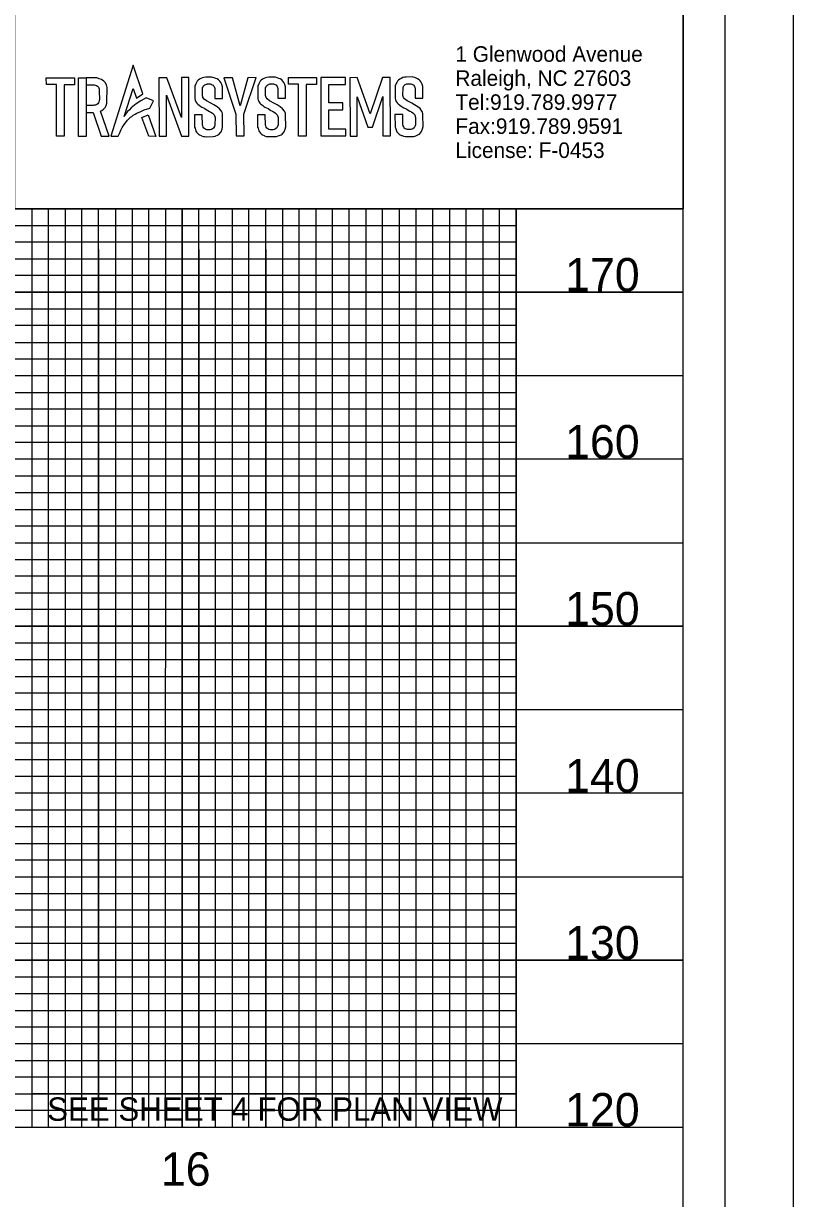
# Model space of a CAD drawing. Extents: x 1779926 to 1781626, y 618464 to 619564.
# Drawn here: x 1781395.5 to 1781626, y 619017.9 to 619369.7 of the extents above; entities that cross this region are included whole.
import ezdxf

# ---------------------------------------------------------------- set-up
doc = ezdxf.new("R2010")
doc.units = 0
for name, color, linetype in [('Exist Vertical Profile Horizontal Axis Label Major', 7, 'Continuous'), ('Exist Vertical Profile Vertical Axis Label', 7, 'Continuous'), ('Old_Level_2', 7, 'Continuous'), ('Old_Level_58', 7, 'Continuous'), ('Prop DSN Text', 7, 'Continuous'), ('Prop Grid Mask', 7, 'Continuous'), ('Prop VPI Ditch Grade Right Label', 7, 'Continuous'), ('Sheet DOT Grid CELL', 7, 'Continuous'), ('Sheet Layout Profile Border Port 1', 7, 'Continuous'), ('Sheet Plot Border Inside CELL', 7, 'Continuous'), ('Sheet Plot Border Outside CELL', 7, 'Continuous'), ('Sheet Profile CELL', 7, 'Continuous'), ('Sheet Profile Grid Major CELL', 7, 'Continuous'), ('Sheet Profile Grid Middle CELL', 7, 'Continuous'), ('Sheet Profile Grid Minor CELL', 7, 'Continuous')]:
    doc.layers.add(name, color=color, linetype=linetype)

msp = doc.modelspace()

# ---------------------------------------------------------------- linework, layer by layer
at = {"layer": 'Old_Level_58'}
msp.add_lwpolyline([(1781392.9, 619378.14), (1781592.95, 619378.14), (1781592.95, 619314.19), (1781392.9, 619314.19)], close=True, dxfattribs=at)
at = {"layer": 'Prop Grid Mask'}
msp.add_lwpolyline([(1781542.96, 619049.19), (1781397.96, 619049.19), (1781397.96, 619039.19), (1781542.96, 619039.19)], close=True, dxfattribs=at)
at = {"layer": 'Prop VPI Ditch Grade Right Label'}
for points in [[(1781428.25, 619357.23), (1781421.58, 619335.89), (1781423.81, 619335.9), (1781424.15, 619336.74), (1781424.72, 619337.9), (1781425.03, 619338.53), (1781425.41, 619339.07), (1781425.93, 619339.83), (1781426.26, 619340.3), (1781426.64, 619340.69), (1781427.02, 619341.08), (1781427.51, 619341.58), (1781427.92, 619341.85), (1781428.33, 619342.18), (1781428.89, 619342.5), (1781429.38, 619342.78), (1781430.6, 619343.35), (1781431.6, 619343.76), (1781433.24, 619344.32), (1781434.38, 619346.46), (1781432.2, 619347.42), (1781430.57, 619346.53), (1781429.19, 619345.63), (1781428.21, 619344.83), (1781427.69, 619344.41), (1781427.15, 619343.84), (1781426.62, 619343.27), (1781426.22, 619342.85), (1781425.84, 619342.2), (1781425.63, 619341.84), (1781428.26, 619350.22), (1781429.26, 619347.33), (1781431.16, 619348.58)], [(1781402.29, 619353.38), (1781410.75, 619353.39), (1781410.75, 619351.31), (1781407.64, 619351.31), (1781407.66, 619335.89), (1781405.31, 619335.89), (1781405.29, 619351.41), (1781402.32, 619351.41)], [(1781411.91, 619353.37), (1781414.22, 619353.38), (1781414.24, 619335.81), (1781411.92, 619335.81)], [(1781414.22, 619351.29), (1781416.61, 619351.29), (1781416.91, 619351.24), (1781417.32, 619351.08), (1781417.64, 619350.86), (1781417.87, 619350.59), (1781418.03, 619350.26), (1781418.15, 619350), (1781418.15, 619349.42), (1781418.16, 619346.93), (1781418.1, 619346.6), (1781418.01, 619346.16), (1781417.88, 619345.86), (1781417.68, 619345.6), (1781417.41, 619345.39), (1781416.99, 619345.24), (1781416.66, 619345.2), (1781416.34, 619345.15), (1781414.23, 619345.14), (1781414.24, 619343.03), (1781416.35, 619343.05), (1781418.72, 619335.88), (1781421.13, 619335.91), (1781418.48, 619343.45), (1781418.86, 619343.58), (1781419.4, 619343.98), (1781419.89, 619344.52), (1781420.23, 619345.15), (1781420.45, 619345.78), (1781420.43, 619345.97), (1781420.48, 619350.53), (1781420.27, 619351.28), (1781419.91, 619351.96), (1781419.5, 619352.43), (1781418.8, 619352.9), (1781418.12, 619353.13), (1781417.45, 619353.35), (1781417.04, 619353.35), (1781414.22, 619353.38)], [(1781436.02, 619353.41), (1781436.03, 619335.95), (1781438.27, 619335.95), (1781438.26, 619348.23), (1781442.71, 619335.93), (1781444.96, 619335.96), (1781444.94, 619353.46), (1781442.76, 619353.46), (1781442.78, 619341.48), (1781438.37, 619353.42)], [(1781452.72, 619347.24), (1781455.03, 619347.24), (1781455.02, 619350.72), (1781454.83, 619351.42), (1781454.55, 619352.01), (1781454.25, 619352.4), (1781453.88, 619352.76), (1781453.44, 619353.04), (1781453.01, 619353.21), (1781453.01, 619353.21), (1781452.55, 619353.41), (1781452.07, 619353.53), (1781451.75, 619353.61), (1781450, 619353.57), (1781449.47, 619353.48), (1781449.02, 619353.4), (1781448.55, 619353.16), (1781448.15, 619352.95), (1781447.76, 619352.67), (1781447.45, 619352.35), (1781447.2, 619351.99), (1781447.01, 619351.59), (1781446.75, 619350.9), (1781446.7, 619350.38), (1781446.7, 619347.21), (1781446.82, 619346.74), (1781447.05, 619346.24), (1781447.34, 619345.83), (1781447.63, 619345.52), (1781448.08, 619345.17), (1781448.54, 619344.83), (1781448.82, 619344.61), (1781449.3, 619344.38), (1781449.79, 619344.16), (1781450.18, 619343.9), (1781450.62, 619343.62), (1781451.15, 619343.35), (1781451.58, 619343.13), (1781452.01, 619342.82), (1781452.32, 619342.52), (1781452.57, 619342.28), (1781452.72, 619341.8), (1781452.82, 619341.5), (1781452.78, 619339.27), (1781452.62, 619338.78), (1781452.38, 619338.36), (1781452.05, 619338.07), (1781451.69, 619337.91), (1781451.35, 619337.84), (1781450.39, 619337.82), (1781450.07, 619337.91), (1781449.74, 619338.1), (1781449.41, 619338.3), (1781449.27, 619338.63), (1781449.13, 619338.97), (1781449.01, 619339.23), (1781448.98, 619342.35), (1781446.64, 619342.32), (1781446.68, 619338.61), (1781446.8, 619338.33), (1781447.07, 619337.46), (1781447.24, 619337.17), (1781447.5, 619336.85), (1781447.88, 619336.48), (1781448.18, 619336.29), (1781448.62, 619336.1), (1781448.78, 619336.04), (1781449.2, 619335.86), (1781449.74, 619335.8), (1781450.13, 619335.76), (1781452.27, 619335.82), (1781452.87, 619335.96), (1781453.69, 619336.33), (1781453.97, 619336.46), (1781454.6, 619337.25), (1781454.93, 619338.04), (1781455.08, 619338.75), (1781455.03, 619342.17), (1781455.02, 619342.64), (1781454.89, 619343.02), (1781454.7, 619343.37), (1781454.16, 619344.13), (1781453.45, 619344.69), (1781452.48, 619345.27), (1781451.73, 619345.71), (1781450.27, 619346.48), (1781449.52, 619347.04), (1781449.19, 619347.46), (1781449.11, 619347.74), (1781449.03, 619348.03), (1781449.08, 619350.46), (1781449.2, 619350.71), (1781449.33, 619350.97), (1781449.51, 619351.12), (1781449.74, 619351.32), (1781450, 619351.42), (1781450.25, 619351.53), (1781450.4, 619351.5), (1781450.42, 619351.58), (1781451.38, 619351.56), (1781451.65, 619351.45), (1781451.93, 619351.34), (1781452.21, 619351.23), (1781452.34, 619351.04), (1781452.52, 619350.76), (1781452.61, 619350.48), (1781452.71, 619350.21), (1781452.7, 619349.9)], [(1781457.99, 619353.42), (1781455.45, 619353.42), (1781459.07, 619342.54), (1781459.1, 619335.99), (1781461.49, 619336.01), (1781461.46, 619342.5), (1781465.12, 619353.46), (1781462.62, 619353.39), (1781460.31, 619345.05)], [(1781471.59, 619347.26), (1781473.9, 619347.26), (1781473.89, 619350.74), (1781473.7, 619351.44), (1781473.42, 619352.03), (1781473.12, 619352.42), (1781472.75, 619352.77), (1781472.31, 619353.06), (1781471.88, 619353.23), (1781471.88, 619353.23), (1781471.43, 619353.42), (1781470.94, 619353.55), (1781470.62, 619353.63), (1781468.87, 619353.59), (1781468.34, 619353.5), (1781467.89, 619353.42), (1781467.43, 619353.18), (1781467.02, 619352.97), (1781466.63, 619352.68), (1781466.32, 619352.37), (1781466.08, 619352.01), (1781465.88, 619351.61), (1781465.63, 619350.91), (1781465.58, 619350.4), (1781465.58, 619347.23), (1781465.69, 619346.75), (1781465.92, 619346.26), (1781466.21, 619345.85), (1781466.51, 619345.54), (1781466.96, 619345.19), (1781467.41, 619344.84), (1781467.69, 619344.62), (1781468.18, 619344.4), (1781468.66, 619344.17), (1781469.05, 619343.92), (1781469.49, 619343.63), (1781470.02, 619343.37), (1781470.45, 619343.15), (1781470.88, 619342.83), (1781471.19, 619342.54), (1781471.44, 619342.3), (1781471.59, 619341.82), (1781471.69, 619341.52), (1781471.65, 619339.28), (1781471.49, 619338.8), (1781471.25, 619338.38), (1781470.92, 619338.09), (1781470.56, 619337.93), (1781470.22, 619337.86), (1781469.26, 619337.84), (1781468.94, 619337.93), (1781468.61, 619338.12), (1781468.28, 619338.31), (1781468.14, 619338.65), (1781468, 619338.98), (1781467.88, 619339.25), (1781467.85, 619342.36), (1781465.51, 619342.34), (1781465.55, 619338.63), (1781465.67, 619338.34), (1781465.94, 619337.48), (1781466.12, 619337.19), (1781466.37, 619336.87), (1781466.75, 619336.5), (1781467.05, 619336.3), (1781467.49, 619336.12), (1781467.65, 619336.05), (1781468.08, 619335.87), (1781468.61, 619335.82), (1781469, 619335.78), (1781471.15, 619335.84), (1781471.74, 619335.98), (1781472.57, 619336.35), (1781472.85, 619336.48), (1781473.47, 619337.27), (1781473.8, 619338.05), (1781473.96, 619338.76), (1781473.9, 619342.19), (1781473.9, 619342.66), (1781473.76, 619343.03), (1781473.57, 619343.39), (1781473.03, 619344.15), (1781472.33, 619344.7), (1781471.35, 619345.28), (1781470.61, 619345.73), (1781469.14, 619346.49), (1781468.39, 619347.06), (1781468.06, 619347.48), (1781467.98, 619347.76), (1781467.91, 619348.05), (1781467.95, 619350.48), (1781468.08, 619350.73), (1781468.2, 619350.99), (1781468.38, 619351.14), (1781468.61, 619351.33), (1781468.87, 619351.44), (1781469.13, 619351.55), (1781469.27, 619351.52), (1781469.29, 619351.59), (1781470.25, 619351.58), (1781470.52, 619351.47), (1781470.8, 619351.36), (1781471.08, 619351.25), (1781471.21, 619351.06), (1781471.39, 619350.78), (1781471.49, 619350.5), (1781471.58, 619350.23), (1781471.57, 619349.92)], [(1781474.74, 619353.45), (1781483.21, 619353.45), (1781483.21, 619351.38), (1781480.1, 619351.38), (1781480.12, 619335.96), (1781477.77, 619335.95), (1781477.75, 619351.48), (1781474.78, 619351.48)], [(1781491.82, 619353.45), (1781484.43, 619353.45), (1781484.45, 619336.02), (1781491.92, 619336.03), (1781491.92, 619338), (1781486.87, 619337.99), (1781486.87, 619343.84), (1781491.08, 619343.84), (1781491.08, 619345.91), (1781486.83, 619345.91), (1781486.83, 619351.41), (1781491.84, 619351.41)], [(1781499.19, 619342.6), (1781495.38, 619353.53), (1781493.17, 619353.42), (1781493.25, 619335.96), (1781495.36, 619335.97), (1781495.31, 619347.65), (1781498.57, 619338.66), (1781499.92, 619338.63), (1781502.99, 619347.76), (1781503.03, 619336.04), (1781505.32, 619336.05), (1781505.25, 619353.47), (1781502.95, 619353.46)], [(1781512.72, 619347.3), (1781515.03, 619347.3), (1781515.03, 619350.77), (1781514.83, 619351.48), (1781514.55, 619352.07), (1781514.25, 619352.46), (1781513.88, 619352.81), (1781513.44, 619353.09), (1781513.02, 619353.27), (1781513.02, 619353.27), (1781512.56, 619353.46), (1781512.08, 619353.58), (1781511.76, 619353.66), (1781510.01, 619353.63), (1781509.48, 619353.54), (1781509.02, 619353.46), (1781508.56, 619353.22), (1781508.15, 619353.01), (1781507.76, 619352.72), (1781507.45, 619352.41), (1781507.21, 619352.04), (1781507.01, 619351.65), (1781506.76, 619350.95), (1781506.71, 619350.44), (1781506.71, 619347.27), (1781506.82, 619346.79), (1781507.05, 619346.3), (1781507.34, 619345.89), (1781507.64, 619345.58), (1781508.09, 619345.23), (1781508.54, 619344.88), (1781508.83, 619344.66), (1781509.31, 619344.44), (1781509.79, 619344.21), (1781510.18, 619343.96), (1781510.62, 619343.67), (1781511.15, 619343.41), (1781511.58, 619343.19), (1781512.01, 619342.87), (1781512.32, 619342.58), (1781512.57, 619342.34), (1781512.73, 619341.86), (1781512.82, 619341.56), (1781512.79, 619339.32), (1781512.62, 619338.84), (1781512.38, 619338.42), (1781512.05, 619338.13), (1781511.7, 619337.97), (1781511.36, 619337.9), (1781510.39, 619337.88), (1781510.07, 619337.97), (1781509.74, 619338.16), (1781509.41, 619338.35), (1781509.27, 619338.69), (1781509.13, 619339.02), (1781509.02, 619339.29), (1781508.98, 619342.4), (1781506.64, 619342.37), (1781506.69, 619338.66), (1781506.8, 619338.38), (1781507.07, 619337.52), (1781507.25, 619337.23), (1781507.5, 619336.91), (1781507.88, 619336.53), (1781508.19, 619336.34), (1781508.62, 619336.16), (1781508.78, 619336.09), (1781509.21, 619335.91), (1781509.74, 619335.86), (1781510.14, 619335.82), (1781512.28, 619335.87), (1781512.87, 619336.01), (1781513.7, 619336.39), (1781513.98, 619336.51), (1781514.6, 619337.31), (1781514.93, 619338.09), (1781515.09, 619338.8), (1781515.04, 619342.22), (1781515.03, 619342.7), (1781514.9, 619343.07), (1781514.71, 619343.43), (1781514.17, 619344.19), (1781513.46, 619344.74), (1781512.48, 619345.32), (1781511.74, 619345.77), (1781510.28, 619346.53), (1781509.52, 619347.09), (1781509.19, 619347.52), (1781509.12, 619347.8), (1781509.04, 619348.08), (1781509.08, 619350.51), (1781509.21, 619350.77), (1781509.33, 619351.02), (1781509.51, 619351.18), (1781509.74, 619351.37), (1781510, 619351.48), (1781510.26, 619351.59), (1781510.41, 619351.56), (1781510.42, 619351.63), (1781511.38, 619351.62), (1781511.66, 619351.51), (1781511.93, 619351.4), (1781512.21, 619351.29), (1781512.34, 619351.09), (1781512.53, 619350.82), (1781512.62, 619350.54), (1781512.71, 619350.26), (1781512.7, 619349.96)], [(1781430.86, 619341.52), (1781432.78, 619342.29), (1781435.04, 619335.85), (1781432.94, 619335.93)]]:
    msp.add_lwpolyline(points, close=True, dxfattribs=at)
at = {"layer": 'Sheet DOT Grid CELL'}
for p, q in [((1781442.96, 619039.19), (1781442.96, 619314.19)), ((1781492.96, 619039.19), (1781492.96, 619314.19)), ((1781542.96, 619039.19), (1781542.96, 619314.19)), ((1781592.96, 619289.19), (1780092.96, 619289.19)), ((1781592.96, 619239.19), (1780092.96, 619239.19)), ((1781592.96, 619189.19), (1780092.96, 619189.19)), ((1781592.96, 619139.19), (1780092.96, 619139.19)), ((1781592.96, 619089.19), (1780092.96, 619089.19))]:
    msp.add_line(p, q, dxfattribs=at)
at = {"layer": 'Sheet Layout Profile Border Port 1'}
msp.add_line((1781542.96, 619049.19), (1781542.96, 619099.19), dxfattribs=at)
for points in [[(1781542.96, 619099.19), (1781542.96, 619314.19), (1781392.91, 619314.19), (1781392.96, 619539.19), (1780142.96, 619539.19), (1780142.96, 619039.19), (1781542.96, 619039.19), (1781542.96, 619049.19)], [(1780142.96, 619378.14), (1780142.96, 619039.19), (1781542.96, 619039.19), (1781542.96, 619314.19)]]:
    msp.add_lwpolyline(points, dxfattribs=at)
at = {"layer": 'Sheet Plot Border Inside CELL'}
msp.add_lwpolyline([(1779938.96, 618486.64), (1781605.46, 618486.64), (1781605.46, 619541.74), (1779938.96, 619541.74)], close=True, dxfattribs=at)
at = {"layer": 'Sheet Plot Border Outside CELL'}
msp.add_lwpolyline([(1779925.96, 618464.19), (1781625.96, 618464.19), (1781625.96, 619564.19), (1779925.96, 619564.19)], close=True, dxfattribs=at)
at = {"layer": 'Sheet Profile CELL'}
msp.add_line((1780092.96, 619039.19), (1781592.96, 619039.19), dxfattribs=at)
msp.add_lwpolyline([(1781592.96, 619539.19), (1780092.96, 619539.19), (1780092.96, 618489.19), (1781592.96, 618489.19)], close=True, dxfattribs=at)
at = {"layer": 'Sheet Profile Grid Major CELL'}
for points in [[(1781542.96, 619314.19), (1781542.96, 619039.19), (1781592.96, 619039.19), (1781592.96, 619389.19)], [(1781392.96, 619339.19), (1780092.96, 619339.19), (1780092.96, 619289.19), (1781592.96, 619289.19)], [(1781442.96, 619314.19), (1781442.96, 619039.19), (1781492.96, 619039.19), (1781492.96, 619039.19), (1781492.96, 619314.19)], [(1781592.96, 619239.19), (1780092.96, 619239.19), (1780092.96, 619189.19), (1781592.96, 619189.19)], [(1781592.96, 619139.19), (1780092.96, 619139.19), (1780092.96, 619139.19), (1780092.96, 619089.19), (1781592.96, 619089.19)]]:
    msp.add_lwpolyline(points, dxfattribs=at)
at = {"layer": 'Sheet Profile Grid Middle CELL'}
for points in [[(1780917.96, 619539.19), (1780967.96, 619539.19), (1780967.96, 619039.19), (1781017.96, 619039.19), (1781017.96, 619539.19), (1781067.96, 619539.19), (1781067.96, 619039.19), (1781117.96, 619039.19), (1781117.96, 619539.19), (1781167.96, 619539.19), (1781167.96, 619039.19), (1781217.96, 619039.19), (1781217.96, 619539.19), (1781267.96, 619539.19), (1781267.96, 619039.19), (1781317.96, 619039.19), (1781317.96, 619539.19), (1781367.96, 619539.19), (1781367.96, 619039.19), (1781417.96, 619039.19), (1781417.96, 619314.19)], [(1781392.91, 619364.19), (1780092.96, 619364.19), (1780092.96, 619314.19), (1781417.96, 619314.19)], [(1781417.96, 619314.19), (1781592.96, 619314.19)], [(1781417.96, 619301.99), (1781417.96, 619039.19), (1781467.96, 619039.19), (1781467.96, 619314.19)], [(1781467.96, 619301.99), (1781467.96, 619039.19), (1781517.96, 619039.19), (1781517.96, 619314.19)], [(1781592.96, 619264.19), (1780092.96, 619264.19), (1780092.96, 619214.19), (1781592.96, 619214.19)], [(1781592.96, 619164.19), (1780092.96, 619164.19), (1780092.96, 619114.19), (1781592.96, 619114.19)], [(1781592.96, 619064.19), (1780092.96, 619064.19)]]:
    msp.add_lwpolyline(points, dxfattribs=at)
at = {"layer": 'Sheet Profile Grid Minor CELL'}
for p, q in [((1781542.96, 619304.19), (1780142.96, 619304.19)), ((1780142.96, 619299.19), (1781542.96, 619299.19)), ((1781542.96, 619294.19), (1780142.96, 619294.19)), ((1780142.96, 619284.19), (1781542.96, 619284.19)), ((1781542.96, 619279.19), (1780142.96, 619279.19)), ((1780142.96, 619274.19), (1781542.96, 619274.19)), ((1781542.96, 619269.19), (1780142.96, 619269.19)), ((1780142.96, 619259.19), (1781542.96, 619259.19)), ((1781542.96, 619254.19), (1780142.96, 619254.19)), ((1780142.96, 619249.19), (1781542.96, 619249.19)), ((1781542.96, 619244.19), (1780142.96, 619244.19)), ((1780142.96, 619234.19), (1781542.96, 619234.19)), ((1781542.96, 619229.19), (1780142.96, 619229.19)), ((1780142.96, 619224.19), (1781542.96, 619224.19)), ((1781542.96, 619219.19), (1780142.96, 619219.19)), ((1780142.96, 619209.19), (1781542.96, 619209.19)), ((1781542.96, 619204.19), (1780142.96, 619204.19)), ((1780142.96, 619199.19), (1781542.96, 619199.19)), ((1781542.96, 619194.19), (1780142.96, 619194.19)), ((1780142.96, 619184.19), (1781542.96, 619184.19)), ((1781542.96, 619179.19), (1780142.96, 619179.19)), ((1780142.96, 619174.19), (1781542.96, 619174.19)), ((1781542.96, 619169.19), (1780142.96, 619169.19)), ((1780142.96, 619159.19), (1781542.96, 619159.19)), ((1781542.96, 619154.19), (1780142.96, 619154.19)), ((1781542.96, 619149.19), (1780142.96, 619149.19)), ((1781542.96, 619144.19), (1780142.96, 619144.19)), ((1780142.96, 619134.19), (1781542.96, 619134.19)), ((1781542.96, 619129.19), (1780142.96, 619129.19)), ((1780142.96, 619124.19), (1781542.96, 619124.19)), ((1781542.96, 619119.19), (1780142.96, 619119.19)), ((1780142.96, 619109.19), (1781542.96, 619109.19)), ((1781542.96, 619104.19), (1780142.96, 619104.19)), ((1780142.96, 619099.19), (1781542.96, 619099.19)), ((1781542.96, 619094.19), (1780142.96, 619094.19)), ((1780142.96, 619084.19), (1781542.96, 619084.19)), ((1781542.96, 619079.19), (1780142.96, 619079.19)), ((1780142.96, 619074.19), (1781542.96, 619074.19)), ((1781542.96, 619069.19), (1780142.96, 619069.19)), ((1780142.96, 619059.19), (1781542.96, 619059.19)), ((1781542.96, 619054.19), (1780142.96, 619054.19)), ((1780142.96, 619049.19), (1781542.96, 619049.19))]:
    msp.add_line(p, q, dxfattribs=at)
for points in [[(1781392.91, 619319.19), (1780142.96, 619319.19), (1780142.96, 619309.19), (1781542.96, 619309.19)], [(1781397.96, 619314.19), (1781397.96, 619039.19), (1781402.96, 619039.19), (1781402.96, 619314.19)], [(1781407.96, 619314.19), (1781407.96, 619039.19), (1781412.96, 619039.19), (1781412.96, 619314.19)], [(1781422.96, 619314.19), (1781422.96, 619039.19), (1781422.96, 619039.19), (1781427.96, 619039.19), (1781432.96, 619039.19), (1781432.96, 619314.19)], [(1781427.96, 619314.19), (1781427.96, 619039.19)], [(1781437.94, 619314.19), (1781437.86, 619039.24), (1781442.86, 619039.24), (1781447.96, 619039.19), (1781447.96, 619314.19)], [(1781447.96, 619301.99), (1781447.96, 619039.19), (1781452.96, 619039.19), (1781452.96, 619314.19)], [(1781457.96, 619314.19), (1781457.96, 619039.19), (1781462.96, 619039.19), (1781462.96, 619314.19)], [(1781472.96, 619314.19), (1781472.96, 619039.19), (1781477.96, 619039.19), (1781477.96, 619314.19)], [(1781482.96, 619314.19), (1781482.96, 619039.19), (1781487.96, 619039.19), (1781487.96, 619314.19)], [(1781497.96, 619314.19), (1781497.96, 619039.19), (1781502.96, 619039.19), (1781502.96, 619314.19)], [(1781507.96, 619314.19), (1781507.96, 619039.19), (1781512.96, 619039.19), (1781512.96, 619314.19)], [(1781522.96, 619314.19), (1781522.96, 619039.19), (1781527.96, 619039.19), (1781527.96, 619314.19)], [(1781532.96, 619314.19), (1781532.96, 619039.19), (1781537.96, 619039.19), (1781537.96, 619314.19)], [(1781542.96, 619044.19), (1780142.96, 619044.19)]]:
    msp.add_lwpolyline(points, dxfattribs=at)

# ---------------------------------------------------------------- texts
at = {"layer": 'Exist Vertical Profile Horizontal Axis Label Major'}
msp.add_text('16', height=10, dxfattribs=at).set_placement((1781436.58, 619021.69))
at = {"layer": 'Exist Vertical Profile Vertical Axis Label'}
for s, p in [('170', (1781557.59, 619289.44)), ('160', (1781557.59, 619239.44)), ('150', (1781557.59, 619189.44)), ('140', (1781557.59, 619139.44)), ('130', (1781557.59, 619089.44)), ('120', (1781557.59, 619039.44))]:
    msp.add_text(s, height=10, dxfattribs=at).set_placement(p)
at = {"layer": 'Old_Level_2'}
for s, p in [('1 Glenwood Avenue', (1781524.75, 619358.18)), ('Raleigh, NC 27603', (1781524.75, 619350.98)), ('Tel:919.789.9977 ', (1781524.75, 619343.79)), ('Fax:919.789.9591', (1781524.75, 619336.59)), ('License: F-0453', (1781524.75, 619329.39))]:
    msp.add_text(s, height=4.6576, rotation=360, dxfattribs=at).set_placement(p)
at = {"layer": 'Prop DSN Text'}
msp.add_text('SEE SHEET 4 FOR PLAN VIEW', height=7, dxfattribs=at).set_placement((1781402.54, 619041.14))

doc.saveas('drawing.dxf')
